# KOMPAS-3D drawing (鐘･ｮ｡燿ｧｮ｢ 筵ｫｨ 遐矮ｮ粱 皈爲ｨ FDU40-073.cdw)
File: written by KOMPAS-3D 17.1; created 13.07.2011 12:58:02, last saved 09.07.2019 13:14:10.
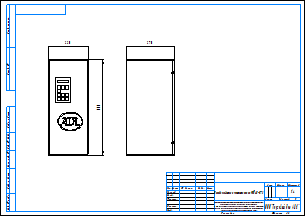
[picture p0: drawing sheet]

Title block, sheet 1: name: Преобразователи частоты серии FDU40-073; scale: 1:4; sheets: 1; sheet format: A3; stored path: \\adlc.lan\data\АДЛ_ПКД\3D-модели\Поставщики\Оборудование Emotron\Преобразователи частоты\Серия FDU 2.0\KOMPAS 2D\Преобразователи частоты серии FDU40-073.cdw

Views: Спереди 1
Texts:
  Рама для чертежей
  Лит-Масса-Масштаб
  Материал-Предприятие
  Масштаб
  Изм.
  Лист
  № докум.
  Подп.
  Дата
  Лит.
  Разраб.
  Пров.
  Т.контр.
  Листов
  Внимание! Данный продукт является объектом авторского права ООО «Торговый Дом АДЛ».
  Запрещается изменение, копирование, распространение
  (в том числе путем копирования на другие сайты и ресурсы в Интернете)
  или любое иное использование информации и объектов без предварительного
  согласия правообладателя (ООО «Торговый Дом АДЛ»).
  Н.контр.
  Утв.
  ООО "Торговый дом АДЛ"
  Изменение
  Номер документа
  Подпись
  Обозначение документа
  Наименование изделия
  Масса изделия по ГОСТ 2.109-73
  Порядковый номер листа
  Общее количество листов в документе
  Характер работы, выполненной лицом, подписавшим документ
  Наименование или индекс предприятия, выпускающего документ
  Инв. № подл.
  Подп. и дата
  Взам. инв. №
  Инв. № дубл.
  Инвентарный номер подлинника по ГОСТ 2.501-68
  Подпись принявшего подлинник в отдел технической документации
  Инвентарный номер подлинника, взамен которого выпущен данный подлинник
  Инвентарный номер дубликата по ГОСТ 2.502-68
  Подпись принявшего дубликат в отдел технической документации
  Справ. №
  Перв. примен.
  Обозначение документа, взамен или на основании которого выпущен данный документ
  Обозначение документа, в котором впервые записан данный документ
  Подпись лица, копировавшего чертеж
  Обозначение формата листа
  !Рама для чертежа
Dimensions and other numbers on the sheet: 220; 270; 530; 1:4; 1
